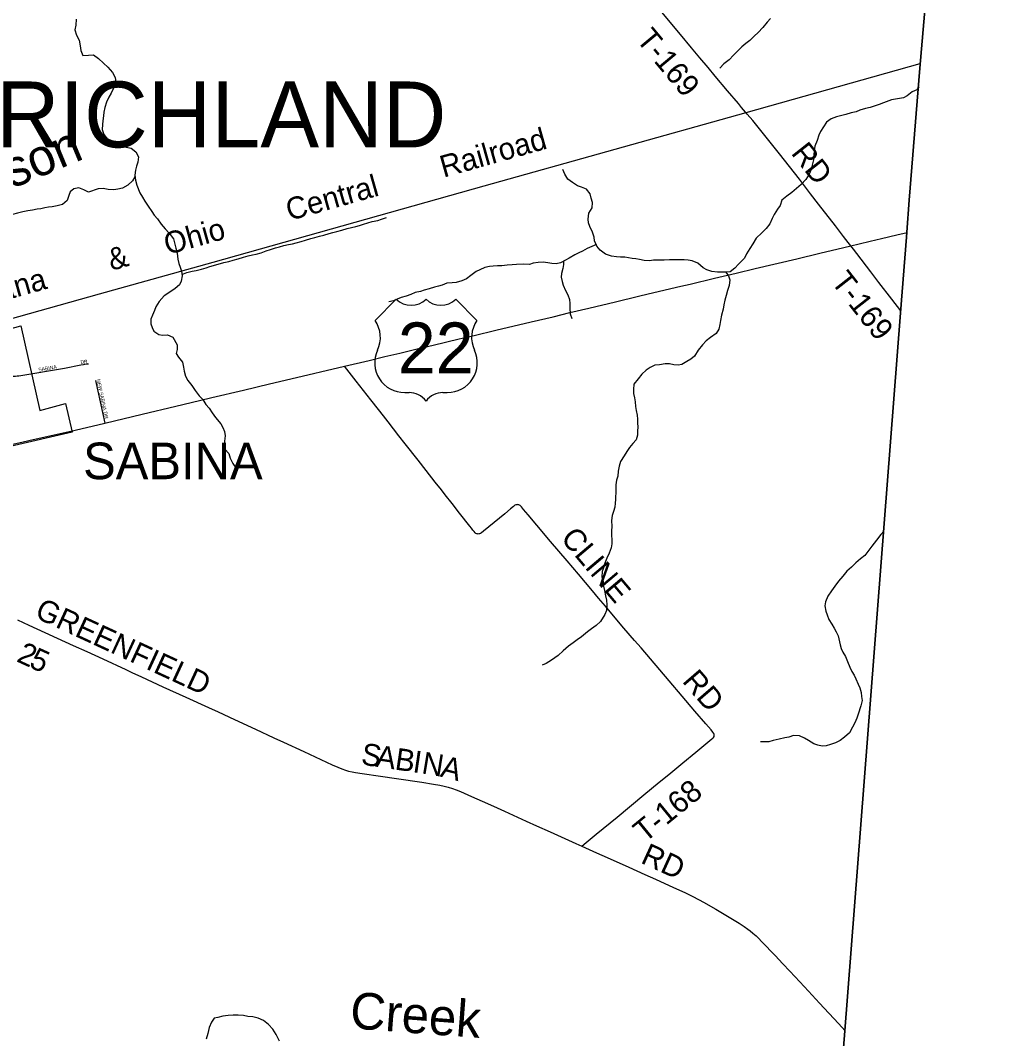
# Model space of a CAD drawing. Extents: x 1442749 to 1756758, y 235267 to 677782.
# Drawn here: x 1651408 to 1664935, y 536724 to 550635 of the extents above; entities that cross this region are included whole.
import ezdxf

# ---------------------------------------------------------------- set-up
doc = ezdxf.new("R2010")
doc.units = 0
for name, color, linetype in [('GM_X_Adjacent_County', 7, 'Continuous'), ('GM_X_City_Street', 7, 'Continuous'), ('GM_X_City_Street_Text', 7, 'Continuous'), ('GM_X_Corporation', 7, 'Continuous'), ('GM_X_Corporation_Text', 7, 'Continuous'), ('GM_X_County', 7, 'Continuous'), ('GM_X_County_Road', 7, 'Continuous'), ('GM_X_County_Road_Text', 7, 'Continuous'), ('GM_X_Minor_River', 7, 'Continuous'), ('GM_X_Minor_River_Text', 7, 'Continuous'), ('GM_X_Rail_Line', 7, 'Continuous'), ('GM_X_Rail_Line_Text', 7, 'Continuous'), ('GM_X_Township', 7, 'Continuous'), ('GM_X_Township_Road', 7, 'Continuous'), ('GM_X_Township_Road_Text', 7, 'Continuous'), ('GM_X_Township_Text', 7, 'Continuous'), ('GM_X_US_Location', 7, 'Continuous'), ('GM_X_US_Route', 7, 'Continuous'), ('GM_X_US_Shield', 7, 'Continuous')]:
    doc.layers.add(name, color=color, linetype=linetype)

msp = doc.modelspace()

# ---------------------------------------------------------------- linework, layer by layer
at = {"layer": 'GM_X_Adjacent_County'}
msp.add_lwpolyline([(1662603, 535965), (1662666, 536773), (1663431, 546640), (1663512, 547675), (1663517, 547743), (1663551, 548179), (1663696, 549983), (1664297, 556947), (1664935, 564290), (1659499, 564802), (1657385, 565000), (1655277, 565199), (1652040, 565503), (1651277, 565574)], dxfattribs=at)
at = {"layer": 'GM_X_City_Street'}
for points in [[(1651126, 545762), (1651190, 545773), (1651226, 545778), (1651242, 545779), (1651256, 545779), (1651272, 545778), (1651307, 545774), (1651327, 545773), (1651342, 545774), (1651365, 545777), (1651389, 545781), (1652010, 545885), (1652236, 545928), (1652271, 545935), (1652290, 545939), (1652313, 545943), (1652330, 545943), (1652337, 545942)], [(1652433, 545716), (1652563, 545134)]]:
    msp.add_lwpolyline(points, dxfattribs=at)
at = {"layer": 'GM_X_Corporation'}
msp.add_lwpolyline([(1650332, 546161), (1651413, 546463), (1651675, 545305), (1652024, 545399), (1652115, 545011), (1651270, 544814)], dxfattribs=at)
at = {"layer": 'GM_X_County'}
msp.add_lwpolyline([(1651277, 565574), (1652040, 565503), (1655277, 565199), (1657385, 565000), (1659499, 564802), (1664935, 564290), (1664297, 556947), (1663696, 549983), (1663551, 548179), (1663517, 547743), (1663512, 547675), (1663431, 546640), (1662666, 536773), (1662603, 535965)], dxfattribs=at)
at = {"layer": 'GM_X_County_Road'}
for points in [[(1651371, 542446), (1651526, 542375), (1651743, 542274), (1651913, 542195), (1652128, 542097), (1652316, 542011), (1652533, 541911), (1652849, 541765), (1652929, 541727), (1653061, 541667), (1653356, 541532), (1653669, 541388), (1653979, 541246), (1654108, 541188), (1654331, 541085), (1654620, 540951), (1654870, 540835), (1655004, 540774), (1655281, 540646), (1655513, 540537), (1655668, 540465), (1655746, 540431), (1655801, 540409), (1655848, 540393), (1655892, 540380), (1655940, 540369), (1655985, 540360), (1656079, 540345), (1656326, 540310), (1656544, 540278), (1656894, 540226), (1657050, 540203), (1657137, 540188), (1657198, 540175), (1657252, 540161), (1657311, 540143), (1657363, 540123), (1657420, 540099), (1657570, 540033), (1657717, 539968), (1657870, 539899), (1658019, 539831), (1658318, 539697), (1658459, 539633), (1658644, 539549), (1658997, 539391), (1659078, 539356)], [(1659078, 539356), (1659129, 539331), (1659278, 539264), (1659425, 539198), (1659554, 539140), (1659629, 539106), (1659718, 539066), (1659937, 538967), (1660083, 538902), (1660331, 538789), (1660483, 538719), (1660583, 538670), (1660682, 538619), (1660740, 538587), (1660908, 538492), (1661043, 538412), (1661226, 538301), (1661294, 538257), (1661345, 538221), (1661379, 538195), (1661414, 538166), (1661459, 538127), (1661489, 538098), (1661537, 538049), (1661717, 537858), (1661821, 537748), (1661918, 537645), (1662054, 537499), (1662173, 537372), (1662322, 537211), (1662583, 536929), (1662674, 536831)]]:
    msp.add_lwpolyline(points, dxfattribs=at)
at = {"layer": 'GM_X_Minor_River'}
for points in [[(1652172, 550651), (1652165, 550570), (1652154, 550506), (1652173, 550432), (1652212, 550363), (1652227, 550289), (1652236, 550222), (1652261, 550156), (1652338, 550161), (1652408, 550166), (1652474, 550113), (1652545, 550050), (1652601, 549995), (1652666, 549924), (1652703, 549853), (1652710, 549789), (1652685, 549717), (1652648, 549641), (1652615, 549585), (1652584, 549518), (1652561, 549446), (1652550, 549380), (1652543, 549330), (1652534, 549262), (1652531, 549211), (1652526, 549145), (1652549, 549077), (1652597, 549012), (1652667, 548989), (1652731, 548958), (1652804, 548911), (1652854, 548902), (1652923, 548891), (1652984, 548838), (1653023, 548771), (1653012, 548699), (1652995, 548643), (1652981, 548589), (1652970, 548519), (1652981, 548451), (1652998, 548384), (1653038, 548281)], [(1661654, 550662), (1661611, 550611), (1661552, 550539), (1661487, 550468), (1661430, 550417), (1661371, 550361), (1661316, 550318), (1661263, 550273), (1661212, 550225), (1661149, 550158), (1661091, 550098), (1661016, 550041), (1660961, 549982)], [(1663679, 549727), (1663653, 549687), (1663588, 549658), (1663521, 549603), (1663470, 549577), (1663389, 549562), (1663307, 549551), (1663196, 549509), (1663141, 549488), (1663070, 549465), (1663014, 549447), (1662951, 549432), (1662875, 549407), (1662824, 549386), (1662757, 549371), (1662683, 549348), (1662630, 549336), (1662558, 549319), (1662485, 549292), (1662418, 549243), (1662377, 549180), (1662336, 549118), (1662317, 549066), (1662292, 548994), (1662262, 548917), (1662251, 548852), (1662245, 548800), (1662242, 548728), (1662225, 548656), (1662216, 548606), (1662185, 548533), (1662137, 548461), (1662074, 548392), (1662011, 548338), (1661946, 548285), (1661879, 548234), (1661811, 548177)], [(1659203, 548208), (1659192, 548266), (1659140, 548329), (1659072, 548358), (1659018, 548375), (1658948, 548420), (1658887, 548465), (1658846, 548532), (1658820, 548596)], [(1652973, 548496), (1652938, 548444), (1652875, 548386), (1652804, 548345), (1652738, 548330), (1652683, 548321), (1652609, 548326), (1652541, 548337), (1652472, 548334), (1652339, 548288), (1652277, 548321), (1652209, 548346), (1652140, 548334), (1652090, 548292)], [(1652090, 548292), (1652069, 548243), (1652049, 548173), (1651984, 548120), (1651912, 548100), (1651844, 548087), (1651793, 548083), (1651741, 548075), (1651689, 548062), (1651639, 548054), (1651573, 548041), (1651508, 548033), (1651442, 548019), (1651368, 548000), (1651301, 547984), (1651245, 547973), (1651181, 547961), (1651119, 547952), (1651050, 547938)], [(1653038, 548281), (1653076, 548220), (1653107, 548165), (1653155, 548095), (1653205, 548026), (1653238, 547976), (1653280, 547926), (1653331, 547853), (1653385, 547789), (1653439, 547726), (1653498, 547651), (1653516, 547577), (1653533, 547523), (1653551, 547453), (1653560, 547374), (1653572, 547314), (1653593, 547264), (1653611, 547208), (1653618, 547144), (1653604, 547073), (1653581, 547022), (1653521, 546974), (1653448, 546924), (1653372, 546871), (1653305, 546793), (1653258, 546723), (1653240, 546671), (1653211, 546609), (1653191, 546555), (1653192, 546491), (1653208, 546439), (1653233, 546387), (1653299, 546344), (1653351, 546336), (1653420, 546337), (1653493, 546305), (1653549, 546204), (1653548, 546138), (1653538, 546084), (1653567, 546032), (1653621, 545967), (1653635, 545897), (1653644, 545845), (1653662, 545776), (1653697, 545716), (1653749, 545645), (1653798, 545577), (1653850, 545508), (1653902, 545454), (1653943, 545389), (1653985, 545339), (1654029, 545275), (1654074, 545208), (1654148, 545123), (1654173, 545071), (1654197, 545019), (1654207, 544959), (1654198, 544888), (1654202, 544834), (1654199, 544778), (1654255, 544718), (1654276, 544655), (1654312, 544583), (1654353, 544521)], [(1661811, 548177), (1661785, 548107), (1661750, 548055), (1661704, 547985), (1661679, 547927), (1661644, 547854), (1661594, 547794), (1661535, 547732), (1661458, 547661), (1661412, 547583), (1661373, 547519), (1661326, 547445), (1661298, 547385), (1661219, 547306), (1661168, 547250), (1661104, 547198), (1661054, 547193), (1660981, 547195), (1660929, 547197), (1660855, 547206), (1660785, 547229), (1660733, 547255), (1660660, 547320), (1660584, 547352), (1660532, 547361), (1660477, 547365), (1660335, 547366), (1660275, 547365), (1660203, 547361), (1660145, 547358), (1660058, 547358), (1660000, 547351), (1659930, 547355), (1659866, 547368), (1659816, 547376), (1659766, 547380), (1659714, 547393), (1659664, 547399), (1659604, 547400), (1659549, 547404), (1659483, 547415), (1659399, 547441), (1659330, 547498), (1659284, 547552), (1659252, 547625), (1659245, 547675), (1659221, 547743), (1659188, 547818), (1659168, 547870), (1659163, 547920), (1659173, 548000), (1659218, 548076), (1659223, 548148), (1659203, 548208)], [(1653616, 547165), (1653681, 547191), (1653753, 547209), (1653808, 547218), (1653884, 547238), (1653946, 547253), (1653998, 547271), (1654111, 547306), (1654189, 547326), (1654256, 547343), (1654316, 547357), (1654382, 547378), (1654457, 547398), (1654519, 547417), (1654579, 547431), (1654631, 547443), (1654696, 547460), (1654768, 547488), (1654826, 547505), (1654893, 547527), (1654949, 547542), (1655009, 547558), (1655072, 547574), (1655124, 547583), (1655174, 547597), (1655242, 547612), (1655305, 547632), (1655377, 547656), (1655431, 547669), (1655492, 547687), (1655554, 547702), (1655624, 547722), (1655678, 547736), (1655733, 547751), (1655801, 547769), (1655873, 547790), (1655932, 547804), (1655990, 547819), (1656040, 547835), (1656096, 547853), (1656155, 547868), (1656215, 547886), (1656289, 547903), (1656340, 547919), (1656408, 547941)], [(1659276, 547571), (1659216, 547547), (1659149, 547517), (1659087, 547480), (1659035, 547458), (1658982, 547430), (1658906, 547387), (1658855, 547361), (1658785, 547322), (1658729, 547310), (1658669, 547312), (1658614, 547321), (1658548, 547331), (1658480, 547328), (1658414, 547316), (1658364, 547301), (1658279, 547305), (1658187, 547302), (1658127, 547296), (1658057, 547289), (1657985, 547283), (1657926, 547282), (1657866, 547276), (1657816, 547273), (1657754, 547257), (1657685, 547226), (1657633, 547204), (1657562, 547148), (1657500, 547103), (1657438, 547079), (1657361, 547054), (1657307, 547048), (1657235, 547045), (1657172, 547019), (1657120, 547005), (1657066, 546990), (1656994, 546966), (1656925, 546951), (1656875, 546931), (1656803, 546917), (1656744, 546892), (1656678, 546868), (1656608, 546847), (1656557, 546825), (1656507, 546805), (1656441, 546788)], [(1658828, 547346), (1658825, 547299), (1658816, 547247), (1658800, 547179), (1658795, 547129), (1658807, 547069), (1658823, 547017), (1658854, 546944), (1658888, 546886), (1658907, 546824), (1658915, 546765), (1658912, 546703), (1658920, 546627), (1658941, 546561)], [(1661046, 547193), (1661081, 547144), (1661097, 547090), (1661090, 547014), (1661066, 546944), (1661047, 546876), (1661030, 546814), (1661018, 546748), (1661007, 546688), (1660985, 546608), (1660970, 546534), (1660962, 546480), (1660947, 546418), (1660913, 546356), (1660834, 546304), (1660777, 546259), (1660727, 546203), (1660668, 546129), (1660617, 546049), (1660567, 546008), (1660512, 545974), (1660442, 545934), (1660392, 545925), (1660332, 545931), (1660274, 545942), (1660215, 545944), (1660139, 545929), (1660075, 545925), (1660011, 545894), (1659958, 545858), (1659898, 545802), (1659845, 545738), (1659786, 545665), (1659782, 545591), (1659785, 545536), (1659795, 545478), (1659804, 545426), (1659810, 545358), (1659819, 545304), (1659833, 545243), (1659840, 545189), (1659840, 545133), (1659842, 545081), (1659839, 545021), (1659837, 544969), (1659818, 544907), (1659776, 544853), (1659729, 544801), (1659691, 544745), (1659658, 544684), (1659605, 544608), (1659587, 544546), (1659574, 544476), (1659570, 544408), (1659549, 544352), (1659541, 544292), (1659542, 544219), (1659537, 544091), (1659535, 544039), (1659528, 543985), (1659512, 543927), (1659491, 543871), (1659481, 543803), (1659486, 543721), (1659481, 543663), (1659483, 543607), (1659486, 543534), (1659486, 543484), (1659476, 543430), (1659449, 543356), (1659418, 543286), (1659394, 543222), (1659373, 543158), (1659357, 543106), (1659352, 543034), (1659368, 542970), (1659375, 542906), (1659389, 542848), (1659402, 542773), (1659416, 542713), (1659419, 542649), (1659415, 542573), (1659392, 542519), (1659331, 542423), (1659273, 542368), (1659210, 542324), (1659154, 542284), (1659075, 542215), (1659016, 542173), (1658960, 542133), (1658895, 542088), (1658821, 542020), (1658754, 541958), (1658665, 541893), (1658591, 541851), (1658536, 541826)], [(1663203, 543657), (1663164, 543611), (1663103, 543536), (1663039, 543452), (1662998, 543396), (1662943, 543326), (1662885, 543277), (1662818, 543225), (1662762, 543167), (1662697, 543110), (1662644, 543040), (1662584, 542974), (1662533, 542907), (1662488, 542841), (1662440, 542771), (1662405, 542693), (1662397, 542637), (1662412, 542565), (1662428, 542512), (1662451, 542450), (1662491, 542386), (1662524, 542333), (1662550, 542283), (1662578, 542227), (1662607, 542106), (1662622, 542056), (1662644, 542006), (1662678, 541947), (1662707, 541877), (1662739, 541801), (1662766, 541742), (1662796, 541692), (1662818, 541640), (1662851, 541567), (1662875, 541515), (1662892, 541453), (1662898, 541397), (1662907, 541342), (1662889, 541270), (1662850, 541156), (1662833, 541102), (1662807, 541037), (1662774, 540981), (1662734, 540903), (1662665, 540845), (1662606, 540797), (1662544, 540764), (1662476, 540742), (1662415, 540725), (1662361, 540719), (1662301, 540732), (1662245, 540752), (1662175, 540797), (1662121, 540831), (1662049, 540860), (1661971, 540864), (1661907, 540845), (1661851, 540833), (1661774, 540816), (1661690, 540798), (1661632, 540781), (1661580, 540777), (1661517, 540780)], [(1654948, 536692), (1654903, 536780), (1654855, 536855), (1654798, 536917), (1654728, 536972), (1654656, 537006), (1654582, 537023), (1654516, 537029), (1654454, 537042), (1654382, 537046), (1654314, 537047), (1654245, 537039), (1654175, 537030), (1654107, 537014), (1654057, 537005), (1654018, 536949), (1653989, 536875), (1653967, 536795), (1653946, 536715)]]:
    msp.add_lwpolyline(points, dxfattribs=at)
at = {"layer": 'GM_X_Rail_Line'}
msp.add_lwpolyline([(1648002, 545615), (1648617, 545811), (1649528, 546067), (1650022, 546206), (1652490, 546899), (1654041, 547333), (1657745, 548373), (1661321, 549378), (1663701, 550047)], dxfattribs=at)
at = {"layer": 'GM_X_Township'}
msp.add_lwpolyline([(1651336, 559084), (1652415, 560044), (1653610, 560758), (1656306, 562370), (1657474, 563039), (1658606, 563902), (1659499, 564802), (1664935, 564290), (1664297, 556947), (1663696, 549983), (1663551, 548179), (1663517, 547743), (1663512, 547675), (1663431, 546640), (1662666, 536773), (1662603, 535965), (1653261, 533457), (1649470, 532440)], dxfattribs=at)
at = {"layer": 'GM_X_Township_Road'}
for points in [[(1662753, 547555), (1662717, 547600), (1662654, 547683), (1662541, 547828), (1662311, 548124), (1662201, 548266), (1662049, 548464), (1661777, 548813), (1661651, 548973), (1661542, 549108), (1661412, 549265), (1661335, 549355), (1661314, 549380), (1661260, 549445), (1661216, 549498), (1661068, 549674), (1660901, 549872), (1660802, 549991), (1660691, 550124), (1660577, 550260), (1660424, 550440), (1660077, 550856)], [(1663437, 546666), (1663312, 546828), (1663136, 547056), (1663024, 547202), (1662833, 547448), (1662787, 547511), (1662753, 547555)], [(1659078, 539356), (1659137, 539405), (1659273, 539518), (1659558, 539751), (1659924, 540054), (1660135, 540227), (1660266, 540335), (1660459, 540494), (1660636, 540640), (1660743, 540727), (1660855, 540818), (1660868, 540829), (1660876, 540840), (1660883, 540852), (1660886, 540862), (1660886, 540876), (1660883, 540886), (1660879, 540895), (1660868, 540912), (1660843, 540943), (1660809, 540983), (1660772, 541025), (1660623, 541200), (1660450, 541401), (1660271, 541611), (1659886, 542063), (1659798, 542165), (1659653, 542334), (1659533, 542474), (1659399, 542631), (1659307, 542742), (1659222, 542842), (1659030, 543071), (1658876, 543254), (1658651, 543515), (1658462, 543738), (1658345, 543879), (1658282, 543955), (1658255, 543988), (1658236, 544007), (1658225, 544014), (1658215, 544018), (1658205, 544019), (1658196, 544020), (1658184, 544018), (1658174, 544015), (1658163, 544010), (1658143, 543993), (1658101, 543960), (1658025, 543896), (1657735, 543655), (1657709, 543635), (1657693, 543624), (1657681, 543620), (1657672, 543619), (1657660, 543617), (1657651, 543619), (1657642, 543621), (1657631, 543627), (1657621, 543635), (1657605, 543651), (1657597, 543662), (1657589, 543672), (1657569, 543698), (1657547, 543727), (1657408, 543905), (1657306, 544034), (1657213, 544153), (1657159, 544222), (1657075, 544328), (1656949, 544488), (1656843, 544625), (1656664, 544852), (1656580, 544961), (1656430, 545152), (1656367, 545232), (1656298, 545319), (1656195, 545451), (1655994, 545707), (1655834, 545910)]]:
    msp.add_lwpolyline(points, dxfattribs=at)
at = {"layer": 'GM_X_US_Route'}
for points in [[(1653073, 545254), (1653531, 545365), (1653854, 545441), (1654023, 545482), (1654457, 545585), (1654812, 545668), (1655102, 545736), (1655834, 545910), (1656171, 545990), (1656385, 546041), (1656590, 546089), (1656829, 546146), (1657046, 546198), (1657400, 546283), (1657605, 546331), (1657902, 546401), (1658384, 546516), (1658684, 546587), (1658913, 546643), (1659172, 546704), (1659536, 546791), (1659852, 546866), (1659983, 546897), (1660430, 547003), (1660557, 547033), (1660889, 547112), (1661186, 547183), (1661445, 547244), (1662013, 547379), (1662329, 547454), (1662658, 547533), (1662753, 547555), (1662865, 547582), (1663018, 547619), (1663172, 547655), (1663382, 547706), (1663520, 547737)], [(1651426, 544872), (1651525, 544895), (1652157, 545039), (1652563, 545134), (1653073, 545254)], [(1649504, 544427), (1649540, 544436), (1649614, 544454), (1649693, 544473), (1649735, 544483), (1650027, 544549), (1650180, 544584), (1650333, 544620), (1650333, 544620), (1650933, 544759), (1650956, 544764), (1651241, 544830), (1651426, 544872)]]:
    msp.add_lwpolyline(points, dxfattribs=at)
at = {"layer": 'GM_X_US_Shield'}
for p, q in [((1656543, 546827), (1656253, 546537)), ((1657645, 546537), (1657355, 546827)), ((1656659, 545551), (1656717, 545551)), ((1657181, 545551), (1657239, 545551))]:
    msp.add_line(p, q, dxfattribs=at)
for centre, radius, start, end in [((1656746, 547034), 290, 225.573, 314.427), ((1657152, 547034), 290, 225.573, 314.427), ((1655920, 546304), 406, 334.5471, 35.0009), ((1657978, 546304), 406, 144.9991, 205.4529), ((1656654, 545957), 406, 154.8319, 270.6383), ((1657244, 545957), 406, 269.3617, 25.1681), ((1656717, 545261), 290, 36.8699, 90), ((1657181, 545261), 290, 90, 143.1301)]:
    msp.add_arc(centre, radius, start, end, dxfattribs=at)

# ---------------------------------------------------------------- texts
at = {"layer": 'GM_X_City_Street_Text'}
for s, rotation, p in [('R', 7.8931, (1652278, 545945)), ('SABINA', 10.0112, (1651659, 545836)), ('D', 9.218, (1652235, 545938)), ('NEW SABINA DR', 282.0215, (1652448, 545728))]:
    msp.add_text(s, height=50, rotation=rotation, dxfattribs=at).set_placement(p)
at = {"layer": 'GM_X_Corporation_Text'}
msp.add_text('SABINA', height=500, rotation=0, dxfattribs=at).set_placement((1652265, 544367))
at = {"layer": 'GM_X_County_Road_Text'}
for s, rotation, p in [('GREENFIELD', 335.2264, (1651590, 542483)), ('2', 335.3494, (1651343, 541883)), ('5', 335.4731, (1651512, 541806)), ('S', 351.6266, (1656052, 540470)), ('A', 351.6319, (1656252, 540441)), ('B', 351.6337, (1656513, 540402)), ('I', 351.5707, (1656757, 540366)), ('N', 350.6036, (1656878, 540349)), ('A', 345.5759, (1657131, 540307)), ('RD', 335.3935, (1659868, 539131))]:
    msp.add_text(s, height=300, rotation=rotation, dxfattribs=at).set_placement(p)
at = {"layer": 'GM_X_Minor_River_Text'}
for s, rotation, p in [('Wilson', 22.5859, (1650441, 547978)), ('Creek', 355.7128, (1655900, 536867))]:
    msp.add_text(s, height=500, rotation=rotation, dxfattribs=at).set_placement(p)
at = {"layer": 'GM_X_Rail_Line_Text'}
for s, rotation, p in [('Railroad', 15.6998, (1657188, 548485)), ('Central', 15.7764, (1655084, 547895)), ('Ohio', 15.6614, (1653417, 547429)), ('&', 16.3101, (1652653, 547212)), ('Indiana', 15.6615, (1650526, 546619))]:
    msp.add_text(s, height=299, rotation=rotation, dxfattribs=at).set_placement(p)
at = {"layer": 'GM_X_Township_Road_Text'}
for s, rotation, p in [('T-169', 309.84, (1659809, 550369)), ('RD', 308.3498, (1661926, 548818)), ('T-169', 308.0476, (1662472, 547062)), ('CLINE', 310.2237, (1658777, 543554)), ('RD', 310.819, (1660438, 541602)), ('T-168', 39.2788, (1659937, 539392))]:
    msp.add_text(s, height=300, rotation=rotation, dxfattribs=at).set_placement(p)
at = {"layer": 'GM_X_Township_Text'}
msp.add_text('RICHLAND', height=900, rotation=0, dxfattribs=at).set_placement((1651075, 548900))
at = {"layer": 'GM_X_US_Location'}
for s in ['0', '/']:
    msp.add_text(s, height=1, dxfattribs=at).set_placement((1656949, 546154))
msp.add_text('22', height=1, rotation=0, dxfattribs=at).set_placement((1656742, 545947))
at = {"layer": 'GM_X_US_Shield'}
msp.add_text('22', height=696.1, dxfattribs=at).set_placement((1656564, 545812))

doc.saveas('drawing.dxf')
